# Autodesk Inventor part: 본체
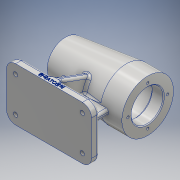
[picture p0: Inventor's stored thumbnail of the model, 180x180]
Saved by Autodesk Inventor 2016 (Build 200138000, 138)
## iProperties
Created: 2018-09
Part Number: 본체
Material: 알루미늄 6061
Document SubType Name: Modeling
Designer: CAMTIC
Density: 2.7 g/cm^3
Appearance: 알루미늄 - 평지
Mass: 737.683 g
Surface Area: 668.641 cm^2
Volume: 273.216 cm^3
Author: CAMTIC
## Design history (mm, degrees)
sketch "스케치1"
  geometry: L1 (56, 35)-(-56, 35); L2 (-56, 35)-(-56, -35); L3 (-56, -35)-(56, -35); L4 (56, -35)-(56, 35); L5 (56, 35)-(-56, -35); L6 (-56, 35)-(56, -35); 1 further point
  constraints: 12 end point, 2 midpoint, 2 parallel, 1 horizontal, 1 perpendicular
  dimensions: "d0" = 112 distance of L3.end L2.end; "d1" = 70 distance of L2.end L1.end
extrude "돌출1" new body sketch "스케치1" distance "d2" = 10; taper "d3" = 0 deg
sketch "스케치3"
  geometry: L1 (56, 74)-(-56, 74); L2 (56, 74)-(56, 108); L3 (56, 108)-(28, 108); L4 (28, 108)-(-52.27, 98.144); L5 (56, 0)-(56, 10) reference; L6 (-56, 0)-(56, 0) reference; L7 (-56, 10)-(56, 10) reference; A1 r 80 centre (24, 74) between (-52.27, 98.144) and (-56, 74); 1 further point
  constraints: 8 end point, 2 horizontal, 2 point on circle, 1 centre point, 1 collinear, 1 parallel, 1 point on line, 1 vertical
  dimensions: "d4" = 112 distance of L1.start L1.end; "d5" = 34 distance of L1.start L2.end; "d6" = 28 distance of L2.end L3.end; "d7" = 173 deg angle of L4 L3; "d8" = 160 diameter of A1; "d9" = 74 distance between parallel lines of L6 L1
revolve "회전1" sketch "스케치3" stored, may be unused: angle "d10" = 90 deg
sketch "스케치4"
  geometry: L1 (-4, 35)-(-4, 4); L2 (-4, 4)-(-38, 4); L3 (-38, 4)-(-38, -4); L4 (-38, -4)-(-4, -4); L5 (-4, -4)-(-4, -35); L6 (-4, -35)-(4, -35); L7 (4, -35)-(4, -4); L8 (4, -4)-(38, -4); L9 (38, -4)-(38, 4); L10 (38, 4)-(4, 4); L11 (4, 35)-(-4, 35); L12 (4, 35)-(4, 4); L13 (0, 49)-(0, -49) reference; L14 (78.4, 0)-(-78.4, 0) reference; L15 (-56, 35)-(-56, -35) reference; L16 (56, -35)-(56, 35) reference; L17 (56, 35)-(-56, 35) reference; L18 (-56, -35)-(56, -35) reference; L19 (-4, 4)-(4, 4); L20 (-4, -4)-(4, -4); 1 further point
  constraints: 28 end point, 8 perpendicular, 8 point on line, 2 collinear, 2 parallel, 1 vertical
  dimensions: "d11" = 8 distance of L11.start L1.start; "d12" = 8 distance of L8.end L9.end; "d13" = 4 distance between parallel lines of L13 L1; "d14" = 4 distance between parallel lines of L8 L14; "d15" = 18 distance between parallel lines of L3 L15; "d16" = 18 distance between parallel lines of L9 L16
extrude "돌출2" join sketch "스케치4" stored distance "d17" = 10; taper "d18" = 0 deg
feature "면 기울기1" dims angle "d23" = 15 deg
sketch "스케치5"
  geometry: C1 r 21 at (0, 0); 1 further point
  constraints: 1 centre point
  dimensions: "d25" = 42 diameter of C1
extrude "돌출5" cut sketch "스케치5" distance "d26" = 15; taper "d27" = 0 deg
sketch "스케치6"
  geometry: C1 r 24 at (0, 0); 1 further point
  constraints: 1 centre point
  dimensions: "d28" = 48 diameter of C1
extrude "돌출6" cut sketch "스케치6" distance "d29" = 54; taper "d30" = 0 deg
sketch "스케치7"
  geometry: C1 r 21 at (0, 0); 1 further point
  constraints: 1 centre point
  dimensions: "d31" = 42 diameter of C1
extrude "돌출7" cut sketch "스케치7" distance "d32" = 12; taper "d33" = 0 deg
sketch "스케치8"
  geometry: C1 r 17.5 at (0, 0); 1 further point
  constraints: 1 centre point
  dimensions: "d34" = 35 diameter of C1
extrude "돌출8" cut sketch "스케치8" distance "d35" = 18; taper "d36" = 0 deg
sketch "스케치9"
  geometry: C1 r 16 at (0, 0); 1 further point
  constraints: 1 centre point
  dimensions: "d37" = 32 diameter of C1
extrude "돌출9" cut sketch "스케치9" distance "d38" = 4; taper "d39" = 0 deg
sketch "스케치10"
  geometry: C1 r 10.5 at (0, 0); 1 further point
  constraints: 1 centre point
  dimensions: "d40" = 21 diameter of C1
extrude "돌출10" cut sketch "스케치10" distance "d41" = 3; taper "d42" = 0 deg
sketch "스케치12"
  geometry: A1 r 26 centre (0, 0) between (0, 26) and (-26, 0); 3 further points
  constraints: 4 point on circle, 1 centre point
  dimensions: "d47" = 52 diameter of A1
hole "구멍1" sketch "스케치12" at (0, 26), (-26, 0), (0, -26), (26, 0) diameter "d48" = 3.242; stored, may be unused: countersink angle "d52" = 90 deg, drill point angle "d54" = 118 deg; dims "d49" = 8, "d50" = 4, "d51" = 2, "d53" = 11
fillet "모깎기10" dims "d69" = 12
sketch "스케치11"
  geometry: L1 (10, 35)-(56.444, 18.096); L2 (10, 35)-(59.424, 35); L3 (56.444, 18.096)-(56.444, -18.096); L4 (0, 23)-(0, 35) reference; L5 (10, 35)-(10, 23) reference; L6 (10, -23)-(10, -35) reference; L7 (10, 35)-(10, -35); L8 (10, -35)-(56.444, -18.096); 2 further points
  constraints: 10 end point, 2 coincident, 1 collinear, 1 equal length, 1 horizontal, 1 parallel
  dimensions: "d79" = 20 deg angle of L1 L2; "d80" = 70 deg angle of L8 L7
extrude "돌출11" join sketch "스케치11" stored distance "d44" = 8; taper "d45" = 0 deg
fillet "모깎기1" dims "d55" = 3, "d56" = 0.3
chamfer "모따기1" distance "d57" = 1; stored, may be unused: second distance "d58" = 2, angle "d59" = 45 deg
hole "구멍3" diameter "d98" = 5.5; stored, may be unused: countersink angle "d102" = 90 deg, drill point angle "d104" = 118 deg; dims "d96" = 10, "d97" = 10, "d99" = 8, "d100" = 9.5, "d101" = 5.4, "d103" = 11
fillet "모깎기24" dims "d105" = 3
fillet "모깎기28" dims "d109" = 3
fillet "모깎기29" dims "d110" = 3
fillet "모깎기30" dims "d111" = 3
fillet "모깎기31" dims "d112" = 3
fillet "모깎기32" dims "d113" = 3
sketch "스케치13"
  geometry: L1 (26.849, 6.316)-(60.032, 6.316); L2 (60.032, 6.316)-(60.032, 1.513); L3 (60.032, 1.513)-(26.849, 1.513); L4 (26.849, 1.513)-(26.849, 6.316); 1 further point
  constraints: 2 other
feature "엠보싱1" sketch "스케치13" dims "d0" = 112, "d1" = 70, "d114" = 0.5, "d115" = 0
sketch "스케치14"
  geometry: C1 r 7.5 at (0, 74) reference; C2 r 24 at (0, 74); 1 further point
  constraints: 1 centre point, 1 coincident
  dimensions: "d116" = 48 diameter of C2
extrude "돌출12" cut sketch "스케치14" distance "d117" = 10; taper "d118" = 0 deg
node "솔리드1"
mirror "대칭3"
mirror "대칭4"
